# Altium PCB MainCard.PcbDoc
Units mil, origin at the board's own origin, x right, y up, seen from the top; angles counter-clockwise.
Board outline 5490 x 3300 mil, 2 copper layers (Top Layer, Bottom Layer); 34 components, 27 nets, 216 pads, 24 vias.
Unrouted connection lines stored in the file: 7.
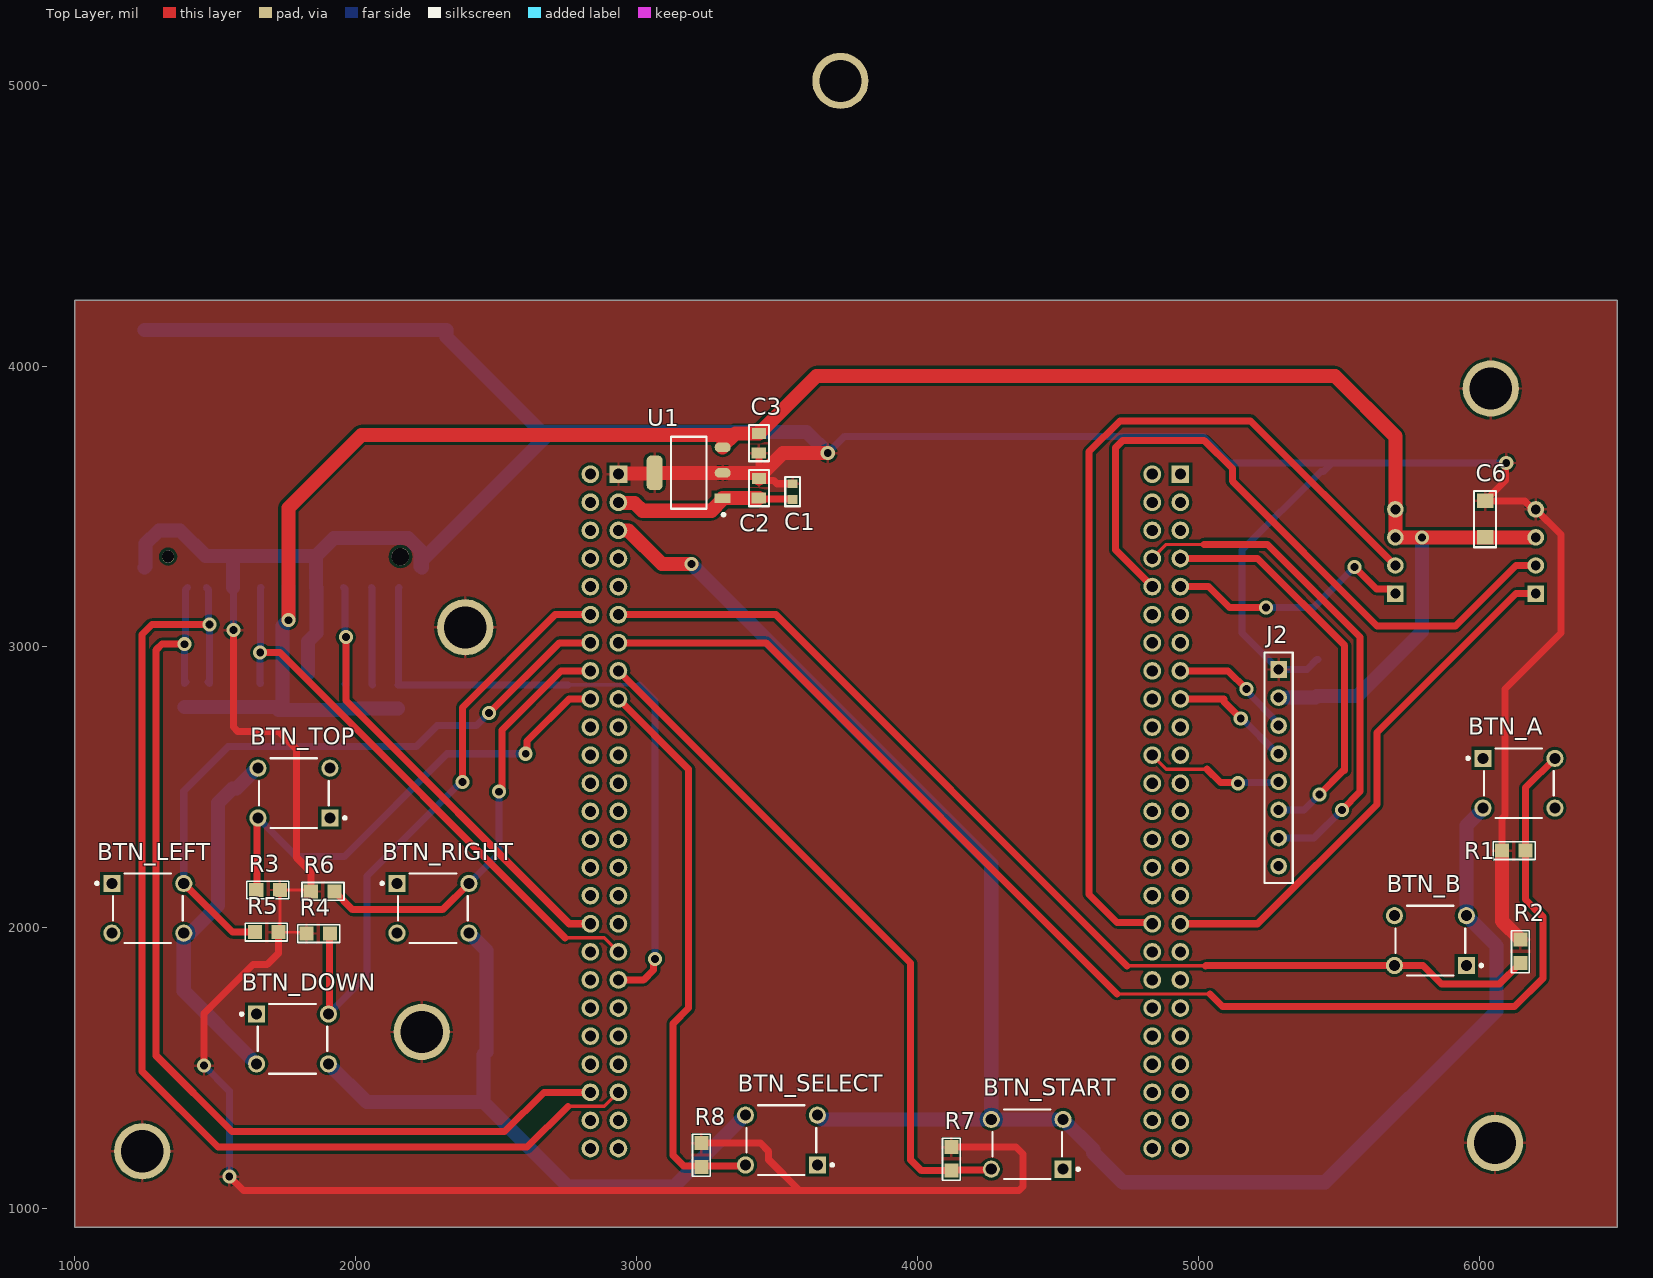
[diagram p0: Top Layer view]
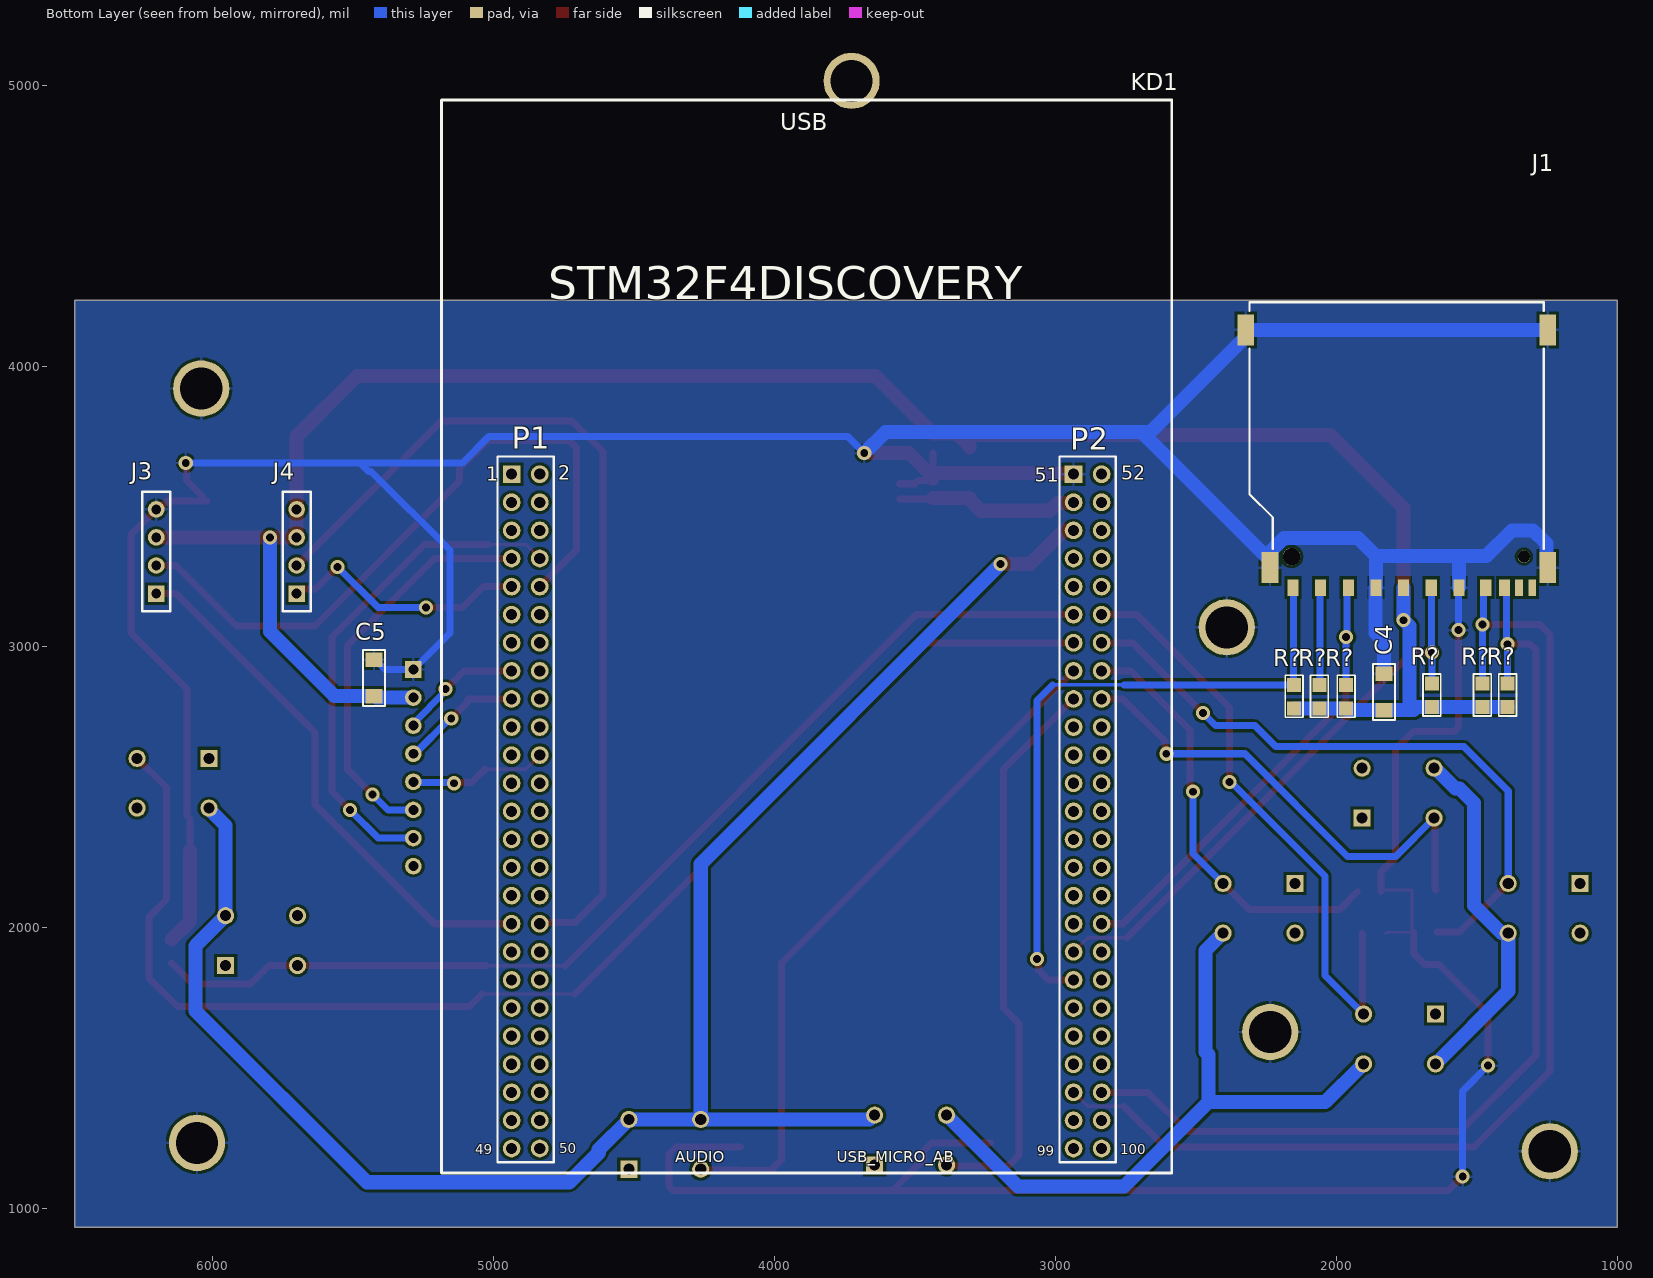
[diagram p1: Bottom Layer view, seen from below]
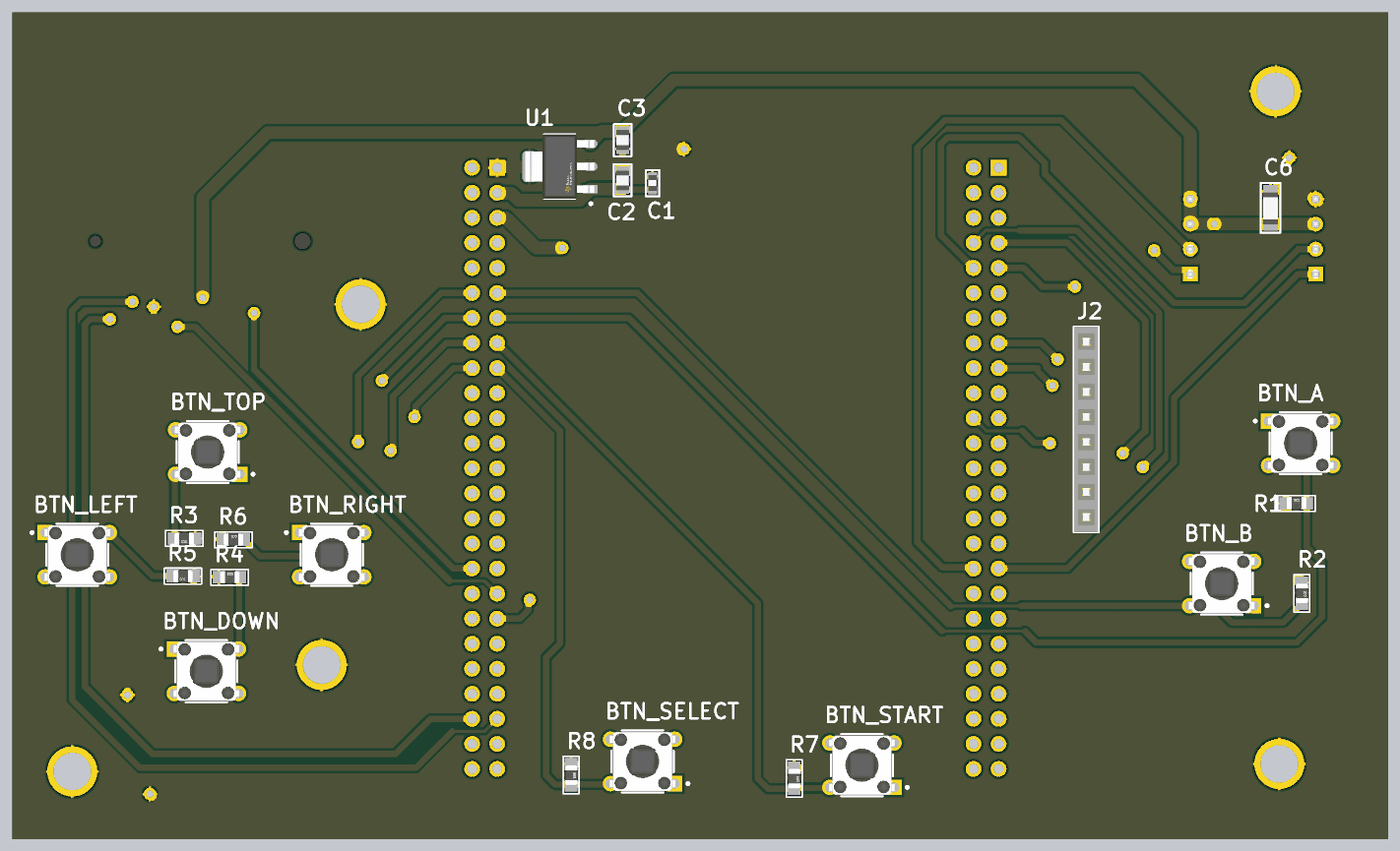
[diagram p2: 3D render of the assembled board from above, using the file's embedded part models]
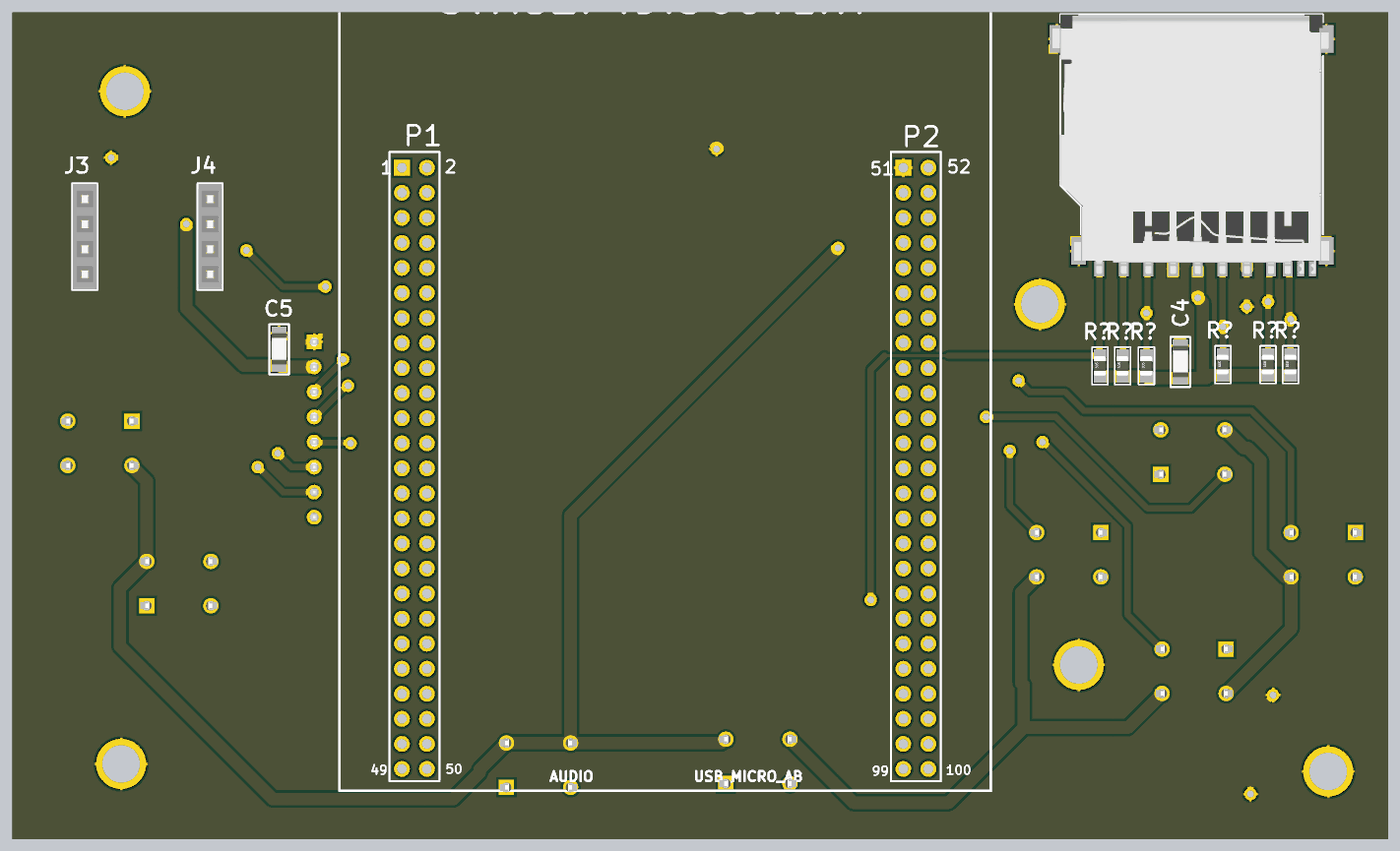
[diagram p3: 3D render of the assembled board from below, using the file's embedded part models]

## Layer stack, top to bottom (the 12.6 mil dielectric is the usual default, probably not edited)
Top Solder: solder mask 0.4, Solder Resist, Dk 3.5
Top Layer: signal copper 1.4
Dielectric 1: dielectric 12.6, FR-4, Dk 4.8
Bottom Layer: signal copper 1.4
Bottom Solder: solder mask 0.4, Solder Resist, Dk 3.5

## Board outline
1000,935 6490,935 6490,4235 1000,4235

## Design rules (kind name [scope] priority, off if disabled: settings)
Clearance [All] p1: gap=10 ignorepadtopadclearanceinfootprint=FALSE except(0: Arc-Hole Track-Hole SMDPad-Hole THPad-Hole Via-Hole Fill-Hole Poly-Hole Region-Hole Text-Hole)
PolygonConnect [All] p1: connectstyle=Relief reliefconductorwidth=10 reliefentries=4 polygonreliefangle="90 Angle" airgapwidth=10
RoutingVias [All] p1: holewidth=28 width=50 viastyle="Through Hole" minholewidth=28 minwidth=50 maxholewidth=28 maxwidth=50
SolderMaskExpansion [All] p1: expansion=4
Width [All] p1: maxlimit=100 minlimit=10 preferedwidth=25
30 further rules are at their usual default settings.

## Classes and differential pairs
component class MainCard: BTN_A BTN_B BTN_DOWN BTN_LEFT BTN_RIGHT BTN_SELECT BTN_START BTN_TOP C1 C2 C3 C4 C5 C6 J1 J2 J3 J4 KD1 R1 R2 R3 R4 R5 R6 R7 R8 R? U1

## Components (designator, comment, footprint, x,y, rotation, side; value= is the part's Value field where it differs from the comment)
BTN_A "BTN_A" FP-1825967-2-MFG 6140,2515 r90 top
BTN_B "BTN_B" FP-1825967-2-MFG 5825,1955 r270 top
BTN_DOWN "BTN_DOWN" FP-1825967-2-MFG 1775,1605 r90 top
BTN_LEFT "BTN_LEFT" FP-1825967-2-MFG 1260,2070 r90 top
BTN_RIGHT "BTN_RIGHT" FP-1825967-2-MFG 2275,2070 r90 top
BTN_SELECT "BTN_SELECT" FP-1825967-2-MFG 3515,1245 r270 top
BTN_START "BTN_START" FP-1825967-2-MFG 4390,1230 r270 top
BTN_TOP "BTN_TOP" FP-1825967-2-MFG 1780,2480 r270 top
C1 "CMS_0603" CONDENSATEUR_CMS_0603 3555,3581 r270 top
C2 "CMS_0805" CONDENSATEUR_CMS_0805 3435.39,3600.47 r270 top value=10µF
C3 "CMS_0805" CONDENSATEUR_CMS_0805 3435,3690 r90 top value=33µF
C4 "CMS_1206" CONDENSATEUR_CMS_1206 1830,2905 r270 bottom value=100nF
C5 "CMS_1206" CONDENSATEUR_CMS_1206 5425,2955 r270 bottom value=100nF
C6 "CMS_1206" CONDENSATEUR_CMS_1206 6020,3390 r90 top value=100nF
J1 "693063010911" 693063010911 1785,3735 r0 bottom
J2 "BARRETTE_8 CONTACTS_1 RANGEE_FEMELLE_DROITE" BARRETTE_8_F_D 5285,2920 r270 top
J3 "BARRETTE_4 CONTACTS_1 RANGEE_FEMELLE_DROITE" BARRETTE_4_F_D 6200,3190 r90 bottom (schematic designator W25L)
J4 "BARRETTE_4 CONTACTS_1 RANGEE_FEMELLE_DROITE" BARRETTE_4_F_D 5700,3190 r90 bottom (schematic designator W25R)
KD1 "STM32F4DISCOVERY" STM32F4DISCOVERY 4935,3615 r180 bottom
R1 "RESISTANCE_CMS_0805" RESISTANCE_CMS_0805 6080,2275 r0 top value=10K
R2 "RESISTANCE_CMS_0805" RESISTANCE_CMS_0805 6145,1959 r270 top value=10K
R3 "RESISTANCE_CMS_0805" RESISTANCE_CMS_0805 1730,2135 r180 top value=10K
R4 "RESISTANCE_CMS_0805" RESISTANCE_CMS_0805 1825,1980 r0 top value=10K
R5 "RESISTANCE_CMS_0805" RESISTANCE_CMS_0805 1725,1985 r180 top value=10K
R6 "RESISTANCE_CMS_0805" RESISTANCE_CMS_0805 1840,2130 r0 top value=10K
R7 "RESISTANCE_CMS_0805" RESISTANCE_CMS_0805 4120,1220 r270 top value=10K
R8 "RESISTANCE_CMS_0805" RESISTANCE_CMS_0805 3230,1234 r270 top value=10K
R? "RESISTANCE_CMS_0805" RESISTANCE_CMS_0805 1965,2781 r90 bottom value=1K
R? "RESISTANCE_CMS_0805" RESISTANCE_CMS_0805 1390,2786 r90 bottom value=1K
R? "RESISTANCE_CMS_0805" RESISTANCE_CMS_0805 2150,2781 r90 bottom value=1K
R? "RESISTANCE_CMS_0805" RESISTANCE_CMS_0805 2060,2781 r90 bottom value=1K
R? "RESISTANCE_CMS_0805" RESISTANCE_CMS_0805 1480,2786 r90 bottom value=1K
R? "RESISTANCE_CMS_0805" RESISTANCE_CMS_0805 1660,2786 r90 bottom value=1K
U1 "LM3940IMP-3.3/NOPB" FP-DCY0004A-IPC_C 3185,3620 r180 top

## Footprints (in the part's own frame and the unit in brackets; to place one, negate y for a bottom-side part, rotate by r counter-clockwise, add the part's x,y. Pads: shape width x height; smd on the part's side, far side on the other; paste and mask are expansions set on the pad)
693063010911 [mm] "SD Card Connector Push & Pull - with Card Detection - 9 Pins"
  rect 1x1.5 smd: 1(6.875,13.3) 2(4.375,13.3) 3(1.875,13.3) 4(-0.625,13.3) 5(-3.125,13.3) 6(-5.625,13.3) 7(-8.05,13.3) 8(-9.75,13.3) 9(9.375,13.3)
  rect 0.7x1.5 smd: CD(-11.05,13.3) WP(-12.25,13.3)
  round 1.1 hole 1.1 unplated: MH1(-11.5,10.5)
  round 1.6 hole 1.6 unplated: MH2(9.5,10.5)
  rect 1.5x2.8 smd: Shield(-13.65,-10) Shield(-13.65,11.5) Shield(11.45,11.5) Shield(13.65,-10)
  silkscreen extent -13.3,-12.5 13.3,9.8, body extent -13.95,-12.5 14.09,13.8, height 3.33
BARRETTE_4_F_D [mm] "BARRETTE 4 CONTACTS ; 1 RANGEE ; DROITE ; FEMELLE ; ESPACEMENT BROCHES = 2.54 mm"
  rect 1.5x1.5 hole 0.9: 1(0,0)
  round 1.5 hole 0.9: 2(2.54,0) 3(5.08,0) 4(7.62,0)
  silkscreen extent -1.6,-1.27 9.2,1.27, body extent -1.53,-1.21 9.13,1.2, height 8.5
BARRETTE_8_F_D [mm] "BARRETTE 8 CONTACTS ; 1 RANGEE ; DROITE ; FEMELLE ; ESPACEMENT BROCHES = 2.54 mm"
  rect 1.5x1.5 hole 0.9: 1(0,0)
  round 1.5 hole 0.9: 2(2.54,0) 3(5.08,0) 4(7.62,0) 5(10.16,0) 6(12.7,0) 7(15.24,0) 8(17.78,0)
  silkscreen extent -1.53,-1.27 19.3,1.27, body extent -1.53,-1.21 19.3,1.2, height 8.5
CONDENSATEUR_CMS_0603 [mm] "CONDENSATEUR CMS 0603 ; DIMENSIONS : 1.6mm x 0.86mm"
  rect 0.8x0.9 smd: 1(0,0) 2(1.422,0)
  silkscreen extent -0.62,-0.67 2.04,0.68, body extent -0.1,-0.46 1.5,0.4, height 0.85
CONDENSATEUR_CMS_0805 [mm] "CONDENSATEUR CMS 0805 ; DIMENSIONS : 2mm x 1.25mm"
  rect 1x1.3 smd: 1(0,0) 2(1.79,-0.01)
  silkscreen extent -0.74,-0.9 2.53,0.89, body extent -0.09,-0.67 1.91,0.64, height 0.73
CONDENSATEUR_CMS_1206 [mil] "CONDENSATEUR CMS 1206 ; DIMENSIONS : 3.2mm x 1.6mm"
  rect 51.18x60 smd: 1(0,0) 2(130,0)
  silkscreen extent -35,-39 165,39, body extent 0,-30 126,31, height 64
FP-1825967-2-MFG [mm]
  rect 1.55x1.55 hole 1 paste-1000 mask+0: 1(2.25,3.25)
  round 1.55 hole 1 paste-1000 mask+0: 2(2.25,-3.25) 3(-2.25,3.25) 4(-2.25,-3.25)
  silkscreen extent -3.15,-3.15 3.15,4.72, body extent -3.25,-4.13 3.25,4.13, height 0.25
FP-DCY0004A-IPC_C [mm]
  rect 1.454x0.873 smd paste+0 mask+0: 1(-3.075,2.3)
  rrect100% 1.454x0.873 smd paste+0 mask+0: 2(-3.075,0) 3(-3.075,-2.3)
  rrect60% 1.454x3.132 smd paste+0 mask+0: 4(3.075,0)
  silkscreen extent -3.27,-3.25 1.6,3.9, body extent -3.9,-3.35 3.9,3.35, height 0.25
RESISTANCE_CMS_0805 [mil] "RESISTANCE CMS 0805 ; DIMENSIONS : 2mm x 1.25mm"
  rect 50x50 smd: 1(0,0) 2(84,0)
  silkscreen extent -31,-31 118,31, body extent 4,-24 83,26, height 31
STM32F4DISCOVERY [mm] "KIT DE DEVELOPPEMENT"
  rect 1.6x1.6 hole 1: 1(0,0) 51(50.8,0)
  round 1.6 hole 1: 2(2.54,0) 3(0,-2.54) 4(2.54,-2.54) 5(0,-5.08) 6(2.54,-5.08) 7(0,-7.62) 8(2.54,-7.62) 9(0,-10.16) 10(2.54,-10.16) 11(0,-12.7) 12(2.54,-12.7) 13(0,-15.24) 14(2.54,-15.24) 15(0,-17.78) 16(2.54,-17.78) 17(0,-20.32) 18(2.54,-20.32) 19(0,-22.86) 20(2.54,-22.86) 21(0,-25.4) 22(2.54,-25.4) 23(0,-27.94) 24(2.54,-27.94) 25(0,-30.48) 26(2.54,-30.48) 27(0,-33.02) 28(2.54,-33.02) 29(0,-35.56) 30(2.54,-35.56) 31(0,-38.1) 32(2.54,-38.1) 33(0,-40.64) 34(2.54,-40.64) 35(0,-43.18) 36(2.54,-43.18) 37(0,-45.72) 38(2.54,-45.72) 39(0,-48.26) 40(2.54,-48.26) 41(0,-50.8) 42(2.54,-50.8) 43(0,-53.34) 44(2.54,-53.34) 45(0,-55.88) 46(2.54,-55.88) 47(0,-58.42) 48(2.54,-58.42) 49(0,-60.96) 50(2.54,-60.96) 52(53.34,0) 53(50.8,-2.54) 54(53.34,-2.54) 55(50.8,-5.08) 56(53.34,-5.08) 57(50.8,-7.62) 58(53.34,-7.62) 59(50.8,-10.16) 60(53.34,-10.16) 61(50.8,-12.7) 62(53.34,-12.7) 63(50.8,-15.24) 64(53.34,-15.24) 65(50.8,-17.78) 66(53.34,-17.78) 67(50.8,-20.32) 68(53.34,-20.32) 69(50.8,-22.86) 70(53.34,-22.86) 71(50.8,-25.4) 72(53.34,-25.4) 73(50.8,-27.94) 74(53.34,-27.94) 75(50.8,-30.48) 76(53.34,-30.48) 77(50.8,-33.02) 78(53.34,-33.02) 79(50.8,-35.56) 80(53.34,-35.56) 81(50.8,-38.1) 82(53.34,-38.1) 83(50.8,-40.64) 84(53.34,-40.64) 85(50.8,-43.18) 86(53.34,-43.18) 87(50.8,-45.72) 88(53.34,-45.72) 89(50.8,-48.26) 90(53.34,-48.26) 91(50.8,-50.8) 92(53.34,-50.8) 93(50.8,-53.34) 94(53.34,-53.34) 95(50.8,-55.88) 96(53.34,-55.88) 97(50.8,-58.42) 98(53.34,-58.42) 99(50.8,-60.96) 100(53.34,-60.96)
  silkscreen extent -6.33,-63.18 59.67,33.82

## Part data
BTN_A BTN_B BTN_DOWN BTN_LEFT BTN_RIGHT BTN_SELECT BTN_START BTN_TOP: library part CMP-03407-000013-1, "SWITCH TACTILE SPST-NO 0.05A 24V", Contact Current Rating=50mA, Contact Resistance=100mR, Max Operating Temperature=105°C, Max Voltage Rating (DC)=24V, Min Operating Temperature=-35°C, Operating Force=160gf, Package Quantity=750
C1: library part CONDENSATEUR_CMS_CER_0603, "CONDENSATEUR CMS CERAMIQUE 0603"
C2 C3: library part CONDENSATEUR_CMS_CER_0805, "CONDENSATEUR CMS CERAMIQUE 0805"
C4 C5 C6: library part CONDENSATEUR_CMS_CER_1206, "CONDENSATEUR CMS CERAMIQUE 1206"
J1: library part CMP-1502-00161-1, "WR-CRD SD Card Connector, Push & Pull, with Card Detection", Manufacturer="Wurth Elektronik", Operating Temperature=-25to85degC, Rated Current=0.5A, Withstanding Voltage=500VAC, Working Voltage=100VAC
J3 J4: "BARRETTE 4 CONTACTS 1 RANGEE FEMELLE DROITE"
KD1: "KIT DE DEVELOPPEMENT POUR MICROCONTROLEUR STM32F407VGT6"
R1 R2 R3 R4 R5 R6 R7 R8 R? R? R? R? R? R?: "RESISTANCE CMS 0805"
U1: library part CMP-0062-01788-4, "IC REG LINEAR 3.3V 1A SOT223-4", Case/Package=SOT-223, Current Rating=1A, Dropout Voltage=500mV, Max Input Voltage=7.5V, Max Operating Temperature=125°C, Max Output Voltage=3.3V, Min Input Voltage=4.5V, Min Operating Temperature=-40°C, Package Quantity=1000, Quiescent Current=15mA

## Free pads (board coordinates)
  round 200 hole 150: 6(1240,1205) 6(1240,1205) 6(2235,1630) 6(2390,3070) 6(3725,5015) 6(6040,3920) 6(6055,1235)

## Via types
v1: diameter 50, hole 28, Top Layer to Bottom Layer, 24 vias

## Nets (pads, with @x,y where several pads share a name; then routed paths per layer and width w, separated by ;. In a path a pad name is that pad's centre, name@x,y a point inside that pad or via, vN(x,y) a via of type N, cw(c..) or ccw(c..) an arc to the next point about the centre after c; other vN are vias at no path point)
3v: BTN_A.3 BTN_A.4 BTN_B.3 BTN_B.4 BTN_DOWN.3 BTN_DOWN.4 BTN_LEFT.3 BTN_LEFT.4 BTN_RIGHT.3 BTN_RIGHT.4 BTN_SELECT.3 BTN_SELECT.4 BTN_START.3 BTN_START.4 BTN_TOP.3 BTN_TOP.4 KD1.55 | length 9981.2
  Top Layer w50: KD1.55 2970,3415 3090,3295 v1(3195,3295) ; BTN_A.3@6012.05,2423.43 BTN_A.3
  Bottom Layer w50: BTN_DOWN.3 1387.95,1775.51 BTN_LEFT.4 1411.42,1981.42 1510,2080 1510,2445 1560.76,2495.76 1576.24,2495.76 1649.06,2568.58 BTN_TOP.4 ; BTN_DOWN.4 2039.37,1380 2445,1380 ; BTN_RIGHT.4 2465,1919.37 2465,1558.74 2455,1548.74 2455,1380 2755,1080 3133.46,1080 BTN_SELECT.4 ; v1(3195,3295) 4262.05,2227.95 BTN_START.4 ; BTN_SELECT.3 3645.94,1333.58 3660.94,1318.58 BTN_START.4 ; BTN_A.3 6012.05,2423.43 5952.95,2364.34 BTN_B.3 6060,1936.54 6060,1705 5450,1095 4730,1095 4625.03,1199.97 4625.03,1211.5 BTN_START.3 BTN_START.4
3v3: C3.2 C4.2 C5.2 C6.1 J1.4 J2.2 J3.3 J4.3 J4.4 R?.1 U1.3 | length 7706.9
  Top Layer w50: v1(1760.39,3095.39) 1760.39,3495.39 2020,3755 3346.33,3755 ; U1.3 3306.06,3714.73 3346.33,3755 ; J3.3 C6.1 v1(5795,3390) J4.3 J4.4 5700,3750 5485,3965 3639.92,3965 3440.71,3765.79 3435.98,3765.79 3435.39,3765.2 C3.2 3434.92,3760 3351.33,3760 3346.33,3755
  Bottom Layer w50: R?.1@1390,2786 1480,2786 1660,2786 1714.59,2786 1725,2775.59 ; J1.4 v1(1760.39,3095.39) 1740,3075 1740,2790.59 1725,2775.59 ; R?.1@2150,2781 2060,2781 1965,2781 1959,2775 C4.2 1829.41,2775.59 1725,2775.59 ; J2.2 5415.59,2820 5420.59,2825 C5.2 5565,2825 5795,3055 v1(5795,3390)
5v: C1.2 C2.2 KD1.53 U1.1 | length 655.6
  Top Layer w25: C2.2 3437.5,3527.5 3552.5,3527.5 C1.2
  Top Layer w50: KD1.53 2937.49,3512.51 2992.49,3512.51 3020,3485 3265.8,3485 3306.06,3525.27 U1.1 3306.34,3529.72 3434.72,3529.72 C2.2
BTN_A: BTN_A.2 KD1.63 R1.2 | length 4719.7
  Top Layer w12: 4710,1765 5040,1765
  Top Layer w25: KD1.63 3460,3015 4710,1765 ; 5040,1765 5085,1720 6125,1720 6225,1820 6225,2040 6164,2101 R1.2 6164,2499.63 BTN_A.2
BTN_B: BTN_B.2 KD1.61 R2.2 | length 3786.9
  Top Layer w12: 4745,1865 5025,1865
  Top Layer w25: KD1.61 3495,3115 4745,1865 ; 5025,1865 5026.42,1866.42 BTN_B.2 5798.58,1866.42 5865,1800 6070,1800 R2.2
BTN_DOWN: BTN_DOWN.2 KD1.62 R4.2 | length 2172.6
  Top Layer w25: BTN_DOWN.2 1905.98,1696.61 1905.98,1976.98 R4.2 ; v1(2380,2520) 2380,2785 2710,3115 KD1.62
  Bottom Layer w25: BTN_DOWN.2 2040,1830.63 2040,2185 2375,2520 v1(2380,2520)
BTN_LEFT: BTN_LEFT.2 KD1.64 R5.2 | length 2319.7
  Top Layer w25: BTN_LEFT.2 1561.54,1985 R5.2 ; v1(2475,2765) 2725,3015 KD1.64
  Bottom Layer w25: BTN_LEFT.2 1387.95,2487.95 1545,2645 2215,2645 2290,2720 2430,2720 v1(2475,2765)
BTN_RIGHT: BTN_RIGHT.2 KD1.66 R6.2 | length 1541.5
  Top Layer w25: R6.2 1989,2065 2309.37,2065 BTN_RIGHT.2 ; v1(2510,2485) 2520,2495 2520,2705 2730,2915 KD1.66
  Bottom Layer w25: BTN_RIGHT.2 2510,2265.63 v1(2510,2485)
BTN_SELECT: BTN_SELECT.2 KD1.67 R8.2 | length 2027.6
  Top Layer w25: KD1.67 3185,2565 3185,1715 3130,1660 3130,1190 3167.5,1152.5 3227.5,1152.5 R8.2 3233.21,1153.21 3383.84,1153.21 BTN_SELECT.2
BTN_START: BTN_START.2 KD1.65 R7.2 | length 2476.2
  Top Layer w25: KD1.65 3975,1875 3975,1175 4014,1136 R7.2 4122.71,1138.71 4259.34,1138.71 BTN_START.2
BTN_TOP: BTN_TOP.2 KD1.68 R3.2 | length 1753.8
  Top Layer w25: R3.2 1649.02,2138.02 1649.02,2388.39 BTN_TOP.2 ; v1(2605,2620) 2609.78,2624.78 2609.78,2664.78 2760,2815 KD1.68
  Bottom Layer w25: BTN_TOP.2 1788.46,2255 1960,2255 2325,2620 v1(2605,2620)
CS: J2.7 KD1.8 | length 1805.7
  Top Layer w12: KD1.8 4885,3365 5020,3365
  Top Layer w25: 5020,3365 5245,3365 5575,3035 5575,2485 v1(5510,2420)
  Bottom Layer w25: J2.7 5410,2320 v1(5510,2420)
CS_2: J3.1 KD1.33 | length 1901.1
  Top Layer w25: KD1.33 5210,2015 5635,2440 5635,2695 6130,3190 J3.1
DC: J2.6 KD1.7 | length 1451.4
  Top Layer w25: KD1.7 5210,3315 5520,3005 5520,2560 5515,2560 v1(5430,2475)
  Bottom Layer w25: J2.6 5375,2420 v1(5430,2475)
GND: C1.1 C2.1 C3.1 C4.1 C5.1 C6.2 J1.3 J1.6 J1.Shield J2.1 J3.4 KD1.51 pad.6@1240,1205 pad.6@2235,1630 pad.6@2390,3070 pad.6@6040,3920 pad.6@6055,1235 R1.1 R2.1 R3.1 R4.1 R5.1 R6.1 R7.1 R8.1 U1.2 U1.4 | length 18052.5
  Top Layer w10: R4.1 1820,1985 R5.1 1730,1990 R3.1 1835,2135 R6.1
  Top Layer w25: v1(1460,1510) 1460,1695 1635,1870 1685,1870 1725,1910 R5.1 ; v1(1550,1115) 1600,1065 3580,1065 ; v1(1565,3060) 1565,2714.64 1579.64,2700 1725,2700 1790,2635 1790,2250 1840,2200 R6.1 ; R8.1 3441,1234 3470,1205 3470,1175 3580,1065 ; C3.1 3435.2,3689.8 3435.2,3605.39 3435.2,3600.67 C2.1 3442.58,3593.29 3487.5,3593.29 3499.78,3581 C1.1 ; R7.1 4350,1220 4375,1195 4375,1079.64 4360.36,1065 3580,1065 ; C6.2 C6.2@6024.41,3520 ; R1.1 6080,2390 6090,2400 6090,2850 6290,3050 6290,3400 J3.4 6190.78,3490 6160.78,3520 C6.2@6024.41,3520 ; v1(6095,3655) 6092.5,3652.5 6092.5,3592.5 6037.5,3537.5 6037.5,3533.09 C6.2@6024.41,3520
  Top Layer w50: KD1.51 2937.5,3617.5 3061.44,3617.5 U1.4 U1.2 3420.59,3620 C2.1@3435.2,3605.39 ; C2.1 3435.39,3605.2 3520.2,3690 v1(3680,3690) ; R1.1 6080,2024 R2.1
  Bottom Layer w25: v1(1460,1510) 1550,1420 v1(1550,1115) ; J1.6 1564.27,3210.65 1564.27,3060.73 v1(1565,3060) ; v1(3680,3690) 3740,3750 5015,3750 5110,3655 5475,3655 ; C5.1 5420.59,2955 5385.59,2920 J2.1 5155,3050 5155,3345 5435,3625 5445,3625 5475,3655 ; v1(6095,3655) 5475,3655
  Bottom Layer w50: J1.Shield@1247.6,3282.24 1252.13,3286.77 1252.13,3367.84 1299.29,3415 1375,3415 1466.19,3323.81 1560,3323.81 ; J1.Shield@1247.6,4128.7 2322.4,4128.7 2322.4,4103.11 2660.51,3765 2692.95,3765 ; J1.6 1563.54,3320.27 1560,3323.81 ; C4.1 1830,3020 1860,3050 1860,3210.19 J1.3 1858.81,3323.81 ; v1(3680,3690) 3605,3765 2692.95,3765 ; 1560,3323.81 1858.81,3323.81 ; 1858.81,3323.81 1923.1,3388.1 2186.56,3388.1 2231.26,3343.4 2231.26,3286.77 2235.79,3282.24 2235.79,3307.83 2692.95,3765
MISO_2: J3.2 KD1.10 | length 2443
  Top Layer w25: KD1.10 4705,3345 4705,3710 4730,3735 5020,3735 5120,3635 5120,3590 5635,3075 5915,3075 6130,3290 J3.2
MOSI_2: J4.1 KD1.9 | length 895.5
  Top Layer w25: KD1.9 5035,3215 5110,3140 v1(5240,3140) ; v1(5555,3285) 5632.97,3207.03 5682.97,3207.03 J4.1
  Bottom Layer w25: v1(5240,3140) 5410,3140 v1(5555,3285)
RES: J2.5 KD1.22 | length 493.5
  Top Layer w12: KD1.22 4885,2565 5030,2565
  Top Layer w25: 5030,2565 5077.5,2517.5 5137.5,2517.5 v1(5140,2515)
  Bottom Layer w25: v1(5140,2515) 5142.5,2517.5 5282.5,2517.5 J2.5
SCL: J2.3 KD1.15 | length 439.6
  Top Layer w25: KD1.15 5105,2915 v1(5170,2850)
  Bottom Layer w25: v1(5170,2850) 5170,2843.24 5285,2728.24 J2.3
SCLK_2: J4.2 KD1.34 | length 3192.1
  Top Layer w25: KD1.34 4830,2020 4710,2020 4610.36,2119.64 4610.36,3695.36 4720,3805 5185,3805 J4.2
SD_CLK: J1.5 KD1.85 R?.2@1660,2870 | length 2059.7
  Top Layer w12: 2745,1965 2885,1965 KD1.85
  Top Layer w25: v1(1660,2980) 1730,2980 2745,1965
  Bottom Layer w25: R?.2@1660.98,2870.98 1660,2870 v1(1660,2980) 1660.98,2980.98 1660.98,3210.4 J1.5
SD_CMD: J1.2 KD1.84 R?.2@1965,2865 | length 1779.4
  Top Layer w25: v1(1965,3035) 1965,2810 2760,2015 KD1.84
  Bottom Layer w25: J1.2 1961.12,3207.5 1961.12,3038.88 v1(1965,3035) 1965,2865 R?.2@1961.12,2868.88
SD_DAT0: J1.7 KD1.95 R?.2@1480,2870 | length 4051.9
  Top Layer w12: 2755,1365 2885,1365 KD1.95
  Top Layer w25: v1(1480,3080) 1275,3080 1240,3045 1240,1490 1510,1220 2610,1220 2755,1365
  Bottom Layer w25: J1.7 1475.22,3204.23 1475.22,3084.78 v1(1480,3080) 1480,2870 R?.2@1474.04,2875.96
SD_DAT1: J1.8 KD1.96 R?.2@1390,2870 | length 3622
  Top Layer w25: v1(1390,3010) 1310,3010 1290,2990 1290,1545 1560,1275 2530,1275 2670,1415 KD1.96
  Bottom Layer w25: R?.2@1395.57,2875.57 1390,2870 v1(1390,3010) 1394.78,3014.78 1394.78,3205.02 J1.8
SD_DAT2: J1.9 KD1.87 R?.2@2150,2865 | length 2387.4
  Top Layer w25: KD1.87 3025,1815 3060.22,1850.22 3060.22,1885.22 v1(3065,1890)
  Bottom Layer w12: 2755,2865 3010,2865
  Bottom Layer w25: J1.9 2152.05,3209.33 2152.05,2867.05 2150,2865 2755,2865 ; 3010,2865 3065,2810 v1(3065,1890)
SD_DAT3: J1.1 KD1.88 R?.2@2060,2865 | length 348.2
  Bottom Layer w25: J1.1 2057.84,3209.22 2057.84,2867.16 R?.2@2060,2865
SDA: J2.4 KD1.17 | length 436.6
  Top Layer w25: KD1.17 5090,2815 5090,2805 v1(5150,2745)
  Bottom Layer w25: v1(5150,2745) 5155,2745 5280,2620 J2.4
pads on no net: BTN_A.1 BTN_B.1 BTN_DOWN.1 BTN_LEFT.1 BTN_RIGHT.1 BTN_SELECT.1 BTN_START.1 BTN_TOP.1 J1.CD J1.MH1 J1.MH2 J1.WP J2.8 KD1.1 KD1.2 KD1.3 KD1.4 KD1.5 KD1.6 KD1.11 KD1.12 KD1.13 KD1.14 KD1.16 KD1.18 KD1.19 KD1.20 KD1.21 KD1.23 KD1.24 KD1.25 KD1.26 KD1.27 KD1.28 KD1.29 KD1.30 KD1.31 KD1.32 KD1.35 KD1.36 KD1.37 KD1.38 KD1.39 KD1.40 KD1.41 KD1.42 KD1.43 KD1.44 KD1.45 KD1.46 KD1.47 KD1.48 KD1.49 KD1.50 KD1.52 KD1.54 KD1.56 KD1.57 KD1.58 KD1.59 KD1.60 KD1.69 KD1.70 KD1.71 KD1.72 KD1.73 KD1.74 KD1.75 KD1.76 KD1.77 KD1.78 KD1.79 KD1.80 KD1.81 KD1.82 KD1.83 KD1.86 KD1.89 KD1.90 KD1.91 KD1.92 KD1.93 KD1.94 KD1.97 KD1.98 KD1.99 KD1.100

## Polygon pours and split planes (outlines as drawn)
GND on Top Layer "TOP_GND" (solid, pour order 2): 1000,4235 6490,4235 6490,935 1000,935
GND on Bottom Layer "BOTTOM_GND" (solid, pour order 4): 1000,4235 6490,4235 6490,935 1000,935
